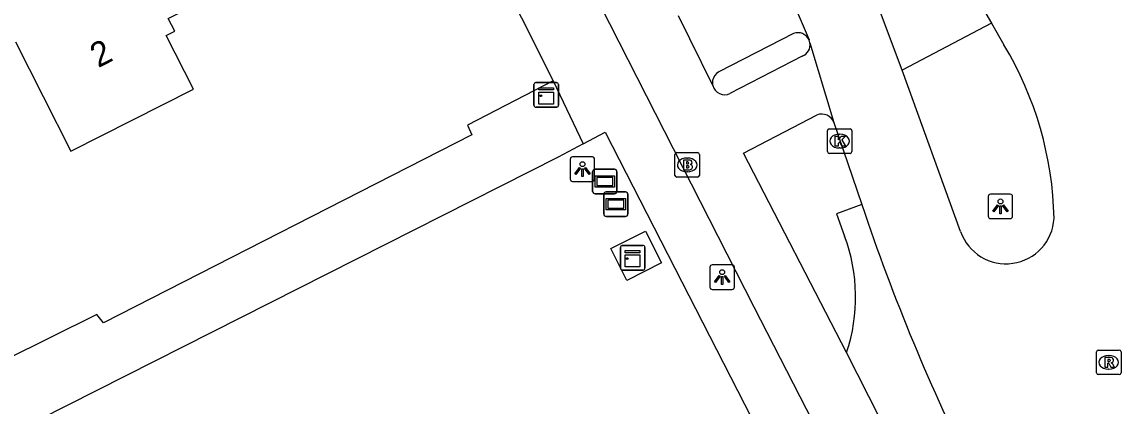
# Model space of a CAD drawing. Extents: x 162417 to 163721, y 384268 to 385416.
# Drawn here: x 163623.31 to 163668.15, y 384814.9 to 384830.56 of the extents above; entities that cross this region are included whole.
import ezdxf

# ---------------------------------------------------------------- set-up
doc = ezdxf.new("R2010")
doc.units = 0
for name, color, linetype in [('IMGEO_Brandkraan', 7, 'Continuous'), ('IMGEO_Fietspad_open', 7, 'Continuous'), ('IMGEO_Kast', 7, 'Continuous'), ('IMGEO_Kolk', 7, 'Continuous'), ('IMGEO_Lichtpunt', 7, 'Continuous'), ('IMGEO_Pand', 7, 'Continuous'), ('IMGEO_Pand_nummerreeks', 7, 'Continuous'), ('IMGEO_Rijbaan_lokaal_gesloten', 7, 'Continuous'), ('IMGEO_Rioolput', 7, 'Continuous'), ('IMGEO_Verklikker', 7, 'Continuous'), ('IMGEO_Voetpad_open', 7, 'Continuous')]:
    doc.layers.add(name, color=color, linetype=linetype)

msp = doc.modelspace()

# ---------------------------------------------------------------- linework, layer by layer
at = {"layer": 'IMGEO_Brandkraan'}
for p, q in [((163649.948, 384824.307), (163649.948, 384825.159)), ((163650.023, 384825.233), (163650.875, 384825.233)), ((163650.436, 384825.013), (163650.461, 384825.013)), ((163650.949, 384825.159), (163650.949, 384824.307)), ((163650.459, 384824.453), (163650.434, 384824.453)), ((163650.875, 384824.233), (163650.023, 384824.233))]:
    msp.add_line(p, q, dxfattribs=at)
for points in [[(163649.948, 384824.307), (163649.948, 384825.159)], [(163650.023, 384825.233), (163650.875, 384825.233)], [(163650.296, 384824.933), (163650.296, 384824.533), (163650.509, 384824.533)], [(163650.527, 384824.933), (163650.296, 384824.933)], [(163650.475, 384824.852), (163650.421, 384824.852), (163650.421, 384824.776)], [(163650.949, 384825.159), (163650.949, 384824.307)], [(163650.421, 384824.776), (163650.474, 384824.776)], [(163650.483, 384824.7), (163650.421, 384824.7), (163650.421, 384824.619)], [(163650.421, 384824.619), (163650.483, 384824.619)], [(163650.875, 384824.233), (163650.023, 384824.233)]]:
    msp.add_lwpolyline(points, dxfattribs=at)
for centre, radius, start, end in [((163650.025, 384825.157), 0.0765, 91.552, 178.448), ((163650.025, 384825.157), 0.0765, 91.552, 178.448), ((163650.476, 384824.814), 0.0379, 267.8285, 90.9355), ((163650.531, 384824.788), 0.145, 59.4692, 91.5367), ((163650.556, 384824.835), 0.0922, 285.5137, 58.1501), ((163650.873, 384825.157), 0.0765, 1.552, 88.448), ((163650.873, 384825.157), 0.0765, 1.552, 88.448), ((163650.484, 384824.659), 0.0404, 269.8759, 90.5077), ((163650.515, 384824.784), 0.251, 268.6676, 293.5347), ((163650.561, 384824.643), 0.105, 301.3115, 78.989), ((163650.025, 384824.309), 0.0765, 181.552, 268.448), ((163650.025, 384824.309), 0.0765, 181.552, 268.448), ((163650.873, 384824.309), 0.0765, 271.552, 358.448), ((163650.873, 384824.309), 0.0765, 271.552, 358.448)]:
    msp.add_arc(centre, radius, start, end, dxfattribs=at)
for centre, major_axis, ratio, start_param, end_param in [((163650.435, 384824.733), (-0.387, 0.002), 0.722429, 4.712389, 7.853982), ((163650.46, 384824.733), (-0.39, 0.002), 0.717154, 1.570796, 4.712389)]:
    msp.add_ellipse(centre, major_axis=major_axis, ratio=ratio, start_param=start_param, end_param=end_param, dxfattribs=at)
at = {"layer": 'IMGEO_Fietspad_open'}
for points in [[(163574.621, 384973.481), (163577.374, 384968.061), (163596.886, 384929.577), (163623.647, 384877.065), (163632.793, 384858.931), (163649.142, 384826.839), (163653.17, 384818.952), (163659.857, 384805.917), (163666.533, 384792.914), (163666.937, 384792.116)], [(163651.496, 384827.967), (163650.098, 384830.808)], [(163662.866, 384830.511), (163659.214, 384828.597)], [(163655.136, 384829.165), (163652.192, 384827.645)], [(163656.954, 384817.08), (163652.741, 384825.213), (163655.748, 384826.772)], [(163663.286, 384804.611), (163656.954, 384817.08)]]:
    msp.add_lwpolyline(points, dxfattribs=at)
for centre, radius, start, end in [((163654.971, 384829.629), 0.492, 289.5873, 9.7566), ((163651.976, 384828.091), 0.495, 194.4639, 295.8814), ((163655.936, 384826.287), 0.52, 18.9234, 111.2274)]:
    msp.add_arc(centre, radius, start, end, dxfattribs=at)
at = {"layer": 'IMGEO_Kast'}
for p, q in [((163644.2, 384827.164), (163644.2, 384828.005)), ((163644.2, 384828.005), (163644.2, 384827.164)), ((163644.275, 384828.089), (163645.116, 384828.089)), ((163645.116, 384828.089), (163644.275, 384828.089)), ((163645.2, 384828.014), (163645.2, 384827.173)), ((163645.2, 384827.173), (163645.2, 384828.014)), ((163645.125, 384827.089), (163644.284, 384827.089)), ((163644.284, 384827.089), (163645.125, 384827.089)), ((163647.724, 384820.522), (163647.724, 384821.363)), ((163647.724, 384821.363), (163647.724, 384820.522)), ((163647.799, 384821.447), (163648.64, 384821.447)), ((163648.64, 384821.447), (163647.799, 384821.447)), ((163648.724, 384821.372), (163648.724, 384820.531)), ((163648.724, 384820.531), (163648.724, 384821.372)), ((163648.649, 384820.447), (163647.808, 384820.447)), ((163647.808, 384820.447), (163648.649, 384820.447))]:
    msp.add_line(p, q, dxfattribs=at)
for points in [[(163644.395, 384827.879), (163644.995, 384827.879), (163644.995, 384827.794), (163644.395, 384827.794), (163644.395, 384827.879)], [(163644.395, 384827.704), (163644.995, 384827.704), (163644.995, 384827.215), (163644.395, 384827.215), (163644.395, 384827.704)], [(163647.919, 384821.237), (163648.519, 384821.237), (163648.519, 384821.152), (163647.919, 384821.152), (163647.919, 384821.237)], [(163647.919, 384821.062), (163648.519, 384821.062), (163648.519, 384820.573), (163647.919, 384820.573), (163647.919, 384821.062)]]:
    msp.add_lwpolyline(points, dxfattribs=at)
for centre in [(163644.479, 384827.553), (163648.003, 384820.911)]:
    msp.add_circle(centre, 0.0377, dxfattribs=at)
for centre, start, end in [((163644.278, 384828.011), 92.4484, 184.2845), ((163644.278, 384828.011), 92.4484, 184.2845), ((163645.122, 384828.011), 2.4484, 94.2845), ((163645.122, 384828.011), 2.4484, 94.2845), ((163644.278, 384827.167), 182.4484, 274.2845), ((163644.278, 384827.167), 182.4484, 274.2845), ((163645.122, 384827.167), 272.4484, 4.2845), ((163645.122, 384827.167), 272.4484, 4.2845), ((163647.802, 384821.369), 92.4484, 184.2845), ((163647.802, 384821.369), 92.4484, 184.2845), ((163648.646, 384821.369), 2.4484, 94.2845), ((163648.646, 384821.369), 2.4484, 94.2845), ((163647.802, 384820.525), 182.4484, 274.2845), ((163647.802, 384820.525), 182.4484, 274.2845), ((163648.646, 384820.525), 272.4484, 4.2845), ((163648.646, 384820.525), 272.4484, 4.2845)]:
    msp.add_arc(centre, 0.0779, start, end, dxfattribs=at)
at = {"layer": 'IMGEO_Kolk'}
for p, q in [((163656.243, 384826.203), (163657.095, 384826.203)), ((163656.168, 384825.277), (163656.168, 384826.129)), ((163656.656, 384825.983), (163656.681, 384825.983)), ((163657.169, 384826.129), (163657.169, 384825.277)), ((163656.679, 384825.423), (163656.654, 384825.423)), ((163657.095, 384825.203), (163656.243, 384825.203))]:
    msp.add_line(p, q, dxfattribs=at)
for points in [[(163656.243, 384826.203), (163657.095, 384826.203)], [(163656.168, 384825.277), (163656.168, 384826.129)], [(163656.489, 384825.903), (163656.612, 384825.903), (163656.612, 384825.752), (163656.742, 384825.903), (163656.906, 384825.903), (163656.76, 384825.752), (163656.913, 384825.503), (163656.761, 384825.503), (163656.676, 384825.667), (163656.612, 384825.6), (163656.612, 384825.503), (163656.489, 384825.503), (163656.489, 384825.903)], [(163657.169, 384826.129), (163657.169, 384825.277)], [(163657.095, 384825.203), (163656.243, 384825.203)]]:
    msp.add_lwpolyline(points, dxfattribs=at)
for centre, start, end in [((163656.245, 384826.127), 91.552, 178.448), ((163656.245, 384826.127), 91.552, 178.448), ((163657.093, 384826.127), 1.552, 88.448), ((163657.093, 384826.127), 1.552, 88.448), ((163656.245, 384825.279), 181.552, 268.448), ((163656.245, 384825.279), 181.552, 268.448), ((163657.093, 384825.279), 271.552, 358.448), ((163657.093, 384825.279), 271.552, 358.448)]:
    msp.add_arc(centre, 0.0765, start, end, dxfattribs=at)
for centre, major_axis, ratio, start_param, end_param in [((163656.655, 384825.703), (-0.387, 0.002), 0.722429, 4.712389, 7.853982), ((163656.68, 384825.703), (-0.39, 0.002), 0.717154, 1.570796, 4.712389)]:
    msp.add_ellipse(centre, major_axis=major_axis, ratio=ratio, start_param=start_param, end_param=end_param, dxfattribs=at)
at = {"layer": 'IMGEO_Lichtpunt'}
for p, q in [((163645.678, 384824.963), (163645.678, 384824.156)), ((163645.678, 384824.963), (163645.678, 384824.156)), ((163646.58, 384825.058), (163645.772, 384825.058)), ((163646.58, 384825.058), (163645.772, 384825.058)), ((163646.674, 384824.156), (163646.674, 384824.963)), ((163646.674, 384824.156), (163646.674, 384824.963)), ((163645.772, 384824.062), (163646.58, 384824.062)), ((163645.772, 384824.062), (163646.58, 384824.062)), ((163663.63, 384823.541), (163662.822, 384823.541)), ((163663.63, 384823.541), (163662.822, 384823.541)), ((163662.728, 384823.446), (163662.728, 384822.639)), ((163662.728, 384823.446), (163662.728, 384822.639)), ((163663.724, 384822.639), (163663.724, 384823.446)), ((163663.724, 384822.639), (163663.724, 384823.446)), ((163662.822, 384822.545), (163663.63, 384822.545)), ((163662.822, 384822.545), (163663.63, 384822.545)), ((163651.379, 384820.561), (163651.379, 384819.754)), ((163651.379, 384820.561), (163651.379, 384819.754)), ((163652.281, 384820.656), (163651.473, 384820.656)), ((163652.281, 384820.656), (163651.473, 384820.656)), ((163652.375, 384819.754), (163652.375, 384820.561)), ((163652.375, 384819.754), (163652.375, 384820.561)), ((163651.473, 384819.66), (163652.281, 384819.66)), ((163651.473, 384819.66), (163652.281, 384819.66))]:
    msp.add_line(p, q, dxfattribs=at)
for points in [[(163646.052, 384824.627), (163646.091, 384824.599), (163645.903, 384824.337), (163645.865, 384824.364), (163646.052, 384824.627)], [(163646.154, 384824.579), (163646.201, 384824.579), (163646.201, 384824.257), (163646.154, 384824.257), (163646.154, 384824.579)], [(163646.264, 384824.599), (163646.302, 384824.626), (163646.489, 384824.364), (163646.45, 384824.336), (163646.264, 384824.599)], [(163663.102, 384823.11), (163663.141, 384823.082), (163662.953, 384822.82), (163662.915, 384822.847), (163663.102, 384823.11)], [(163663.204, 384823.062), (163663.251, 384823.062), (163663.251, 384822.74), (163663.204, 384822.74), (163663.204, 384823.062)], [(163663.314, 384823.082), (163663.352, 384823.109), (163663.539, 384822.847), (163663.5, 384822.819), (163663.314, 384823.082)], [(163651.753, 384820.225), (163651.792, 384820.197), (163651.604, 384819.935), (163651.566, 384819.962), (163651.753, 384820.225)], [(163651.855, 384820.177), (163651.902, 384820.177), (163651.902, 384819.855), (163651.855, 384819.855), (163651.855, 384820.177)], [(163651.965, 384820.197), (163652.003, 384820.224), (163652.19, 384819.962), (163652.151, 384819.934), (163651.965, 384820.197)]]:
    msp.add_lwpolyline(points, dxfattribs=at)
for centre in [(163646.177, 384824.761), (163663.227, 384823.244), (163651.878, 384820.359)]:
    msp.add_circle(centre, 0.0994, dxfattribs=at)
for centre, start, end in [((163645.772, 384824.963), 90, 180), ((163645.772, 384824.963), 90, 180), ((163646.58, 384824.963), 0, 90), ((163646.58, 384824.963), 0, 90), ((163645.772, 384824.156), 180, 270), ((163645.772, 384824.156), 180, 270), ((163646.58, 384824.156), 270, 0), ((163646.58, 384824.156), 270, 360), ((163662.822, 384823.446), 90, 180), ((163662.822, 384823.446), 90, 180), ((163663.63, 384823.446), 0, 90), ((163663.63, 384823.446), 0, 90), ((163662.822, 384822.639), 180, 270), ((163662.822, 384822.639), 180, 270), ((163663.63, 384822.639), 270, 0), ((163663.63, 384822.639), 270, 360), ((163651.473, 384820.561), 90, 180), ((163651.473, 384820.561), 90, 180), ((163652.281, 384820.561), 0, 90), ((163652.281, 384820.561), 0, 90), ((163651.473, 384819.754), 180, 270), ((163651.473, 384819.754), 180, 270), ((163652.281, 384819.754), 270, 0), ((163652.281, 384819.754), 270, 360)]:
    msp.add_arc(centre, 0.0946, start, end, dxfattribs=at)
at = {"layer": 'IMGEO_Pand'}
msp.add_lwpolyline([(163623.052, 384829.751), (163625.307, 384825.288), (163630.309, 384827.816), (163629.199, 384830.011), (163629.543, 384830.185), (163629.284, 384830.696), (163634.575, 384833.37), (163631.906, 384838.651)], dxfattribs=at)
at = {"layer": 'IMGEO_Rijbaan_lokaal_gesloten'}
for points in [[(163654.225, 384832.489), (163654.727, 384831.463), (163655.422, 384829.827)], [(163661.529, 384832.793), (163662.866, 384830.511)], [(163659.214, 384828.597), (163658.178, 384831.388)], [(163662.866, 384830.511), (163663.37, 384829.622)], [(163655.456, 384829.712), (163656.428, 384826.456)], [(163661.602, 384822.02), (163659.214, 384828.597)], [(163656.428, 384826.456), (163657.574, 384823.116)]]:
    msp.add_lwpolyline(points, dxfattribs=at)
for centre, radius, start, end in [((163655.008, 384829.642), 0.454, 8.8789, 24.0619), ((163651.151, 384822.257), 14.267, 1.1939, 31.0799), ((163737.354, 384849.77), 84.115, 198.47399, 206.66449), ((163663.455, 384822.666), 1.963, 199.2072, 356.7374)]:
    msp.add_arc(centre, radius, start, end, dxfattribs=at)
at = {"layer": 'IMGEO_Rioolput'}
for p, q in [((163667.219, 384817.184), (163668.071, 384817.184)), ((163667.144, 384816.258), (163667.144, 384817.11)), ((163667.632, 384816.964), (163667.657, 384816.964)), ((163668.145, 384817.11), (163668.145, 384816.258)), ((163667.655, 384816.404), (163667.63, 384816.404)), ((163668.071, 384816.184), (163667.219, 384816.184))]:
    msp.add_line(p, q, dxfattribs=at)
for points in [[(163667.219, 384817.184), (163668.071, 384817.184)], [(163667.144, 384816.258), (163667.144, 384817.11)], [(163667.733, 384816.882), (163667.481, 384816.884), (163667.481, 384816.484)], [(163667.659, 384816.803), (163667.605, 384816.803), (163667.605, 384816.722)], [(163668.145, 384817.11), (163668.145, 384816.258)], [(163667.481, 384816.484), (163667.605, 384816.484), (163667.605, 384816.646), (163667.616, 384816.646)], [(163667.605, 384816.722), (163667.657, 384816.722)], [(163667.663, 384816.617), (163667.734, 384816.484), (163667.874, 384816.484), (163667.809, 384816.61)], [(163668.071, 384816.184), (163667.219, 384816.184)]]:
    msp.add_lwpolyline(points, dxfattribs=at)
for centre, radius, start, end in [((163667.221, 384817.108), 0.0765, 91.552, 178.448), ((163667.221, 384817.108), 0.0765, 91.552, 178.448), ((163668.069, 384817.108), 0.0765, 1.552, 88.448), ((163668.069, 384817.108), 0.0765, 1.552, 88.448), ((163667.665, 384816.707), 0.0964, 77.0061, 93.1865), ((163667.679, 384816.764), 0.0378, 276.6634, 79.6772), ((163667.732, 384816.772), 0.109, 350.3612, 89.416), ((163667.73, 384816.772), 0.112, 277.5842, 350.9817), ((163667.615, 384816.593), 0.0533, 26.0293, 88.6989), ((163667.641, 384816.911), 0.19, 274.7715, 282.9687), ((163667.714, 384816.557), 0.108, 29.5134, 73.7905), ((163667.221, 384816.26), 0.0765, 181.552, 268.448), ((163667.221, 384816.26), 0.0765, 181.552, 268.448), ((163668.069, 384816.26), 0.0765, 271.552, 358.448), ((163668.069, 384816.26), 0.0765, 271.552, 358.448)]:
    msp.add_arc(centre, radius, start, end, dxfattribs=at)
for centre, major_axis, ratio, start_param, end_param in [((163667.631, 384816.684), (-0.387, 0.002), 0.722429, 4.712389, 7.853982), ((163667.656, 384816.684), (-0.39, 0.002), 0.717154, 1.570796, 4.712389)]:
    msp.add_ellipse(centre, major_axis=major_axis, ratio=ratio, start_param=start_param, end_param=end_param, dxfattribs=at)
at = {"layer": 'IMGEO_Verklikker'}
for p, q in [((163646.593, 384823.655), (163646.593, 384824.455)), ((163646.593, 384824.455), (163646.593, 384823.655)), ((163646.693, 384824.555), (163647.483, 384824.555)), ((163647.483, 384824.555), (163646.693, 384824.555)), ((163647.583, 384824.455), (163647.583, 384823.655)), ((163647.583, 384823.655), (163647.583, 384824.455)), ((163647.483, 384823.555), (163646.693, 384823.555)), ((163646.693, 384823.555), (163647.483, 384823.555)), ((163647.044, 384822.734), (163647.044, 384823.534)), ((163647.044, 384823.534), (163647.044, 384822.734)), ((163647.144, 384823.634), (163647.934, 384823.634)), ((163647.934, 384823.634), (163647.144, 384823.634)), ((163648.034, 384823.534), (163648.034, 384822.734)), ((163648.034, 384822.734), (163648.034, 384823.534)), ((163647.934, 384822.634), (163647.144, 384822.634)), ((163647.144, 384822.634), (163647.934, 384822.634))]:
    msp.add_line(p, q, dxfattribs=at)
for points in [[(163646.694, 384824.287), (163647.482, 384824.287), (163647.482, 384823.823), (163646.694, 384823.823), (163646.694, 384824.287)], [(163646.759, 384824.222), (163646.759, 384823.888), (163647.417, 384823.888), (163647.417, 384824.222), (163646.759, 384824.222)], [(163647.145, 384823.366), (163647.933, 384823.366), (163647.933, 384822.902), (163647.145, 384822.902), (163647.145, 384823.366)], [(163647.21, 384823.301), (163647.21, 384822.967), (163647.868, 384822.967), (163647.868, 384823.301), (163647.21, 384823.301)]]:
    msp.add_lwpolyline(points, dxfattribs=at)
for centre, start, end in [((163646.693, 384824.455), 90, 180), ((163646.693, 384824.455), 90, 180), ((163647.483, 384824.455), 0, 90), ((163647.483, 384824.455), 360, 90), ((163646.693, 384823.655), 180, 270), ((163646.693, 384823.655), 180, 270), ((163647.144, 384823.534), 90, 180), ((163647.144, 384823.534), 90, 180), ((163647.483, 384823.655), 270, 0), ((163647.483, 384823.655), 270, 0), ((163647.934, 384823.534), 0, 90), ((163647.934, 384823.534), 360, 90), ((163647.144, 384822.734), 180, 270), ((163647.144, 384822.734), 180, 270), ((163647.934, 384822.734), 270, 0), ((163647.934, 384822.734), 270, 0)]:
    msp.add_arc(centre, 0.1, start, end, dxfattribs=at)
at = {"layer": 'IMGEO_Voetpad_open'}
for points in [[(163534.443, 385045.503), (163557.559, 385000), (163571.782, 384971.962), (163572.96, 384969.64), (163599.332, 384917.655), (163619.201, 384879.411), (163644.977, 384828.162)], [(163654.789, 384830.088), (163651.735, 384828.523)], [(163644.977, 384828.162), (163641.486, 384826.348), (163641.667, 384825.959), (163626.635, 384818.288), (163626.367, 384818.629), (163618.849, 384814.904), (163579.211, 384794.807)], [(163644.977, 384828.162), (163646.209, 384825.591)], [(163646.209, 384825.591), (163647.107, 384826.065), (163654.204, 384812.214)], [(163646.209, 384825.591), (163645.189, 384825.054), (163624.002, 384814.334), (163630.865, 384800.823)], [(163657.574, 384823.116), (163656.536, 384822.745), (163656.87, 384821.834)], [(163647.988, 384820.027), (163647.336, 384821.327), (163648.751, 384822.037), (163649.403, 384820.737), (163647.988, 384820.027)]]:
    msp.add_lwpolyline(points, dxfattribs=at)
for centre, radius, start, end in [((163654.97, 384829.628), 0.494, 23.7169, 111.4682), ((163651.979, 384828.089), 0.498, 119.3137, 170.264), ((163651.969, 384828.089), 0.489, 170.0503, 194.3977), ((163650.174, 384819.338), 7.146, 341.58, 20.4445)]:
    msp.add_arc(centre, radius, start, end, dxfattribs=at)

# ---------------------------------------------------------------- texts
at = {"layer": 'IMGEO_Pand_nummerreeks'}
msp.add_text('2', height=1, rotation=26.8144, dxfattribs=at).set_placement((163626.423, 384828.675))

doc.saveas('drawing.dxf')
